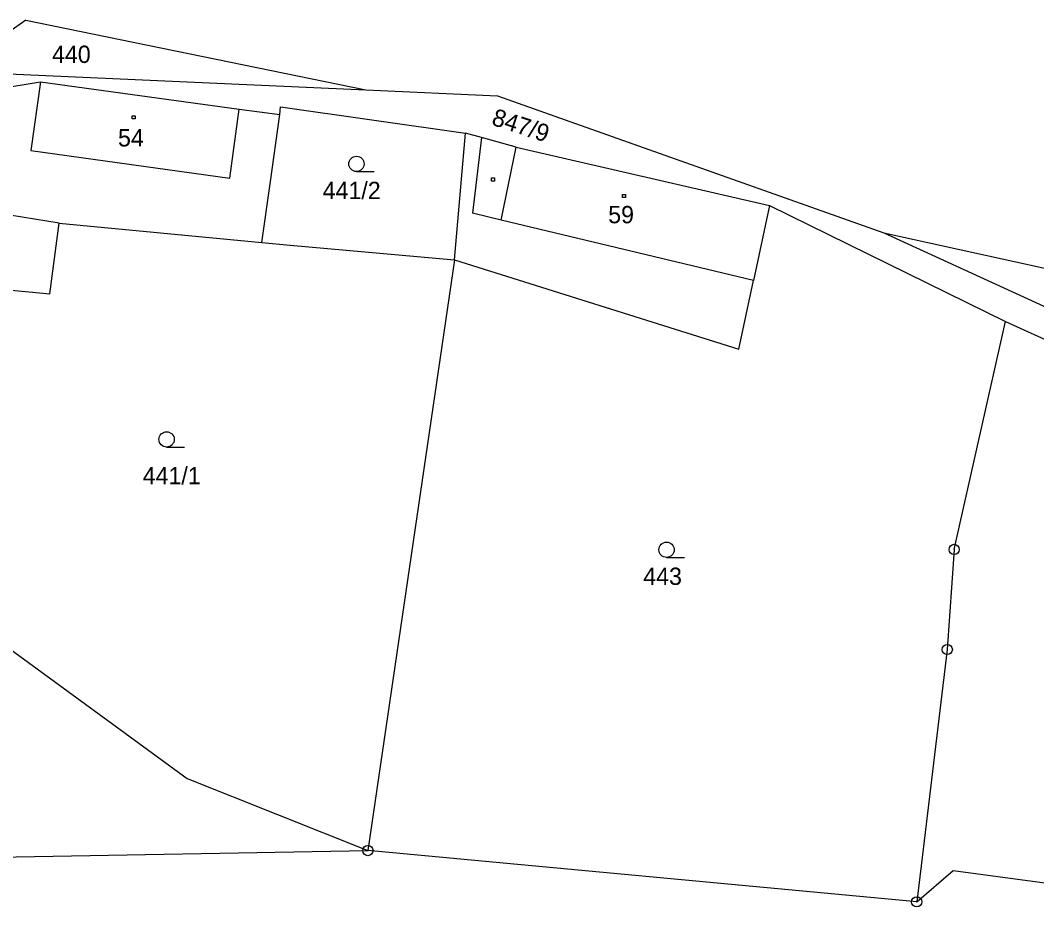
# Model space of a CAD drawing. Extents: x -791032 to -787751, y -1106872 to -1104403.
# Drawn here: x -789032.3 to -788932.6, y -1105221.6 to -1105132.8 of the extents above; entities that cross this region are included whole.
import ezdxf

# ---------------------------------------------------------------- set-up
doc = ezdxf.new("R2010")
doc.units = 0
for name, color, linetype in [('Vrstva 1', 7, 'Continuous'), ('Vrstva 14', 7, 'Continuous'), ('Vrstva 15', 7, 'Continuous'), ('Vrstva 2', 7, 'Continuous'), ('Vrstva 23', 7, 'Continuous'), ('Vrstva 25', 7, 'Continuous'), ('Vrstva 28', 7, 'Continuous')]:
    doc.layers.add(name, color=color, linetype=linetype)

msp = doc.modelspace()

# ---------------------------------------------------------------- linework, layer by layer
at = {"layer": 'Vrstva 1'}
for p, q in [((-789031.72, -1105132.84), (-789035.34, -1105135.33)), ((-789031.72, -1105132.84), (-788998.39, -1105139.67)), ((-789034.14, -1105138.05), (-788998.39, -1105139.67)), ((-789039.24, -1105140.29), (-789030.3, -1105138.87)), ((-789030.3, -1105138.87), (-789010.81, -1105141.54)), ((-788998.39, -1105139.67), (-788985.51, -1105140.26)), ((-788985.51, -1105140.26), (-788947.63, -1105153.68)), ((-789010.81, -1105141.54), (-789006.85, -1105142.08)), ((-789006.85, -1105142.08), (-789006.76, -1105141.33)), ((-789006.76, -1105141.33), (-788988.64, -1105143.89)), ((-789007.79, -1105148.86), (-789006.85, -1105142.08)), ((-788989.72, -1105156.34), (-788988.64, -1105143.89)), ((-788987.06, -1105144.33), (-788988.64, -1105143.89)), ((-788983.67, -1105145.29), (-788987.06, -1105144.33)), ((-788983.67, -1105145.29), (-788958.84, -1105151.01)), ((-789008.59, -1105154.62), (-789007.79, -1105148.86)), ((-789028.47, -1105152.73), (-789039.66, -1105150.91)), ((-788958.84, -1105151.01), (-788960.41, -1105158.36)), ((-788958.84, -1105151.01), (-788935.69, -1105162.36)), ((-789029.37, -1105159.67), (-789028.47, -1105152.73)), ((-789028.47, -1105152.73), (-789008.59, -1105154.62)), ((-788947.63, -1105153.68), (-788907.93, -1105162.37)), ((-788947.63, -1105153.68), (-788906.32, -1105172.61)), ((-789008.59, -1105154.62), (-789005.82, -1105154.88)), ((-789005.82, -1105154.88), (-788989.72, -1105156.34)), ((-788989.72, -1105156.34), (-788998.2, -1105214.25)), ((-788989.72, -1105156.34), (-788961.85, -1105165.09)), ((-788961.85, -1105165.09), (-788960.41, -1105158.36)), ((-789040.54, -1105158.6), (-789029.37, -1105159.67)), ((-788940.73, -1105184.72), (-788935.69, -1105162.36)), ((-788935.69, -1105162.36), (-788905.31, -1105176.29)), ((-788940.73, -1105184.72), (-788941.4, -1105194.53)), ((-789040.23, -1105189.41), (-789015.91, -1105207.18)), ((-788941.4, -1105194.53), (-788944.4, -1105219.27)), ((-789015.91, -1105207.18), (-788998.2, -1105214.25)), ((-789070.94, -1105215.53), (-788998.2, -1105214.25)), ((-788944.4, -1105219.27), (-788998.2, -1105214.25)), ((-788944.4, -1105219.27), (-788940.81, -1105216.19)), ((-788940.81, -1105216.19), (-788892.13, -1105222.86))]:
    msp.add_line(p, q, dxfattribs=at)
at = {"layer": 'Vrstva 2'}
for p, q in [((-789030.3, -1105138.87), (-789031.24, -1105145.61)), ((-789011.74, -1105148.31), (-789010.81, -1105141.54)), ((-788987.06, -1105144.33), (-788987.94, -1105151.76)), ((-788985.12, -1105152.44), (-788983.67, -1105145.29)), ((-789031.24, -1105145.61), (-789011.74, -1105148.31)), ((-788985.12, -1105152.44), (-788987.94, -1105151.76)), ((-788960.41, -1105158.36), (-788985.12, -1105152.44))]:
    msp.add_line(p, q, dxfattribs=at)
at = {"layer": 'Vrstva 23'}
for p, q in [((-788999.32, -1105147.67), (-788997.57, -1105147.67)), ((-789017.93, -1105174.68), (-789016.18, -1105174.68)), ((-788968.92, -1105185.5), (-788967.17, -1105185.5))]:
    msp.add_line(p, q, dxfattribs=at)
for centre in [(-788999.32, -1105146.92), (-789017.93, -1105173.93), (-788968.92, -1105184.75)]:
    msp.add_circle(centre, 0.75, dxfattribs=at)
at = {"layer": 'Vrstva 25'}
for p, q in [((-789021.32, -1105142.19), (-789021.02, -1105142.19)), ((-789021.32, -1105142.49), (-789021.32, -1105142.19)), ((-789021.02, -1105142.49), (-789021.32, -1105142.49)), ((-789021.02, -1105142.19), (-789021.02, -1105142.49)), ((-788986.08, -1105148.3), (-788985.78, -1105148.3)), ((-788986.08, -1105148.6), (-788986.08, -1105148.3)), ((-788985.78, -1105148.3), (-788985.78, -1105148.6)), ((-788985.78, -1105148.6), (-788986.08, -1105148.6)), ((-788973.25, -1105149.91), (-788972.95, -1105149.91)), ((-788973.25, -1105150.21), (-788973.25, -1105149.91)), ((-788972.95, -1105150.21), (-788973.25, -1105150.21)), ((-788972.95, -1105149.91), (-788972.95, -1105150.21))]:
    msp.add_line(p, q, dxfattribs=at)
at = {"layer": 'Vrstva 28'}
for centre, radius in [((-788940.73, -1105184.72), 0.5), ((-788940.73, -1105184.72), 0.01), ((-788941.4, -1105194.53), 0.5), ((-788941.4, -1105194.53), 0.01), ((-788998.2, -1105214.25), 0.5), ((-788998.2, -1105214.25), 0.01), ((-788944.4, -1105219.27), 0.5), ((-788944.4, -1105219.27), 0.01)]:
    msp.add_circle(centre, radius, dxfattribs=at)

# ---------------------------------------------------------------- texts
at = {"layer": 'Vrstva 14'}
for s, p in [('440', (-789029.168, -1105137.02)), ('441/2', (-789002.635, -1105150.37)), ('441/1', (-789020.278, -1105178.34)), ('443', (-788971.208, -1105188.2))]:
    msp.add_text(s, height=1.7, dxfattribs=at).set_placement(p)
msp.add_text('847/9', height=1.7, rotation=341.94789, dxfattribs=at).set_placement((-788986.169, -1105143.058))
at = {"layer": 'Vrstva 15'}
for s, p in [('54', (-789022.699, -1105145.21)), ('59', (-788974.643, -1105152.74))]:
    msp.add_text(s, height=1.7, dxfattribs=at).set_placement(p)

doc.saveas('drawing.dxf')
